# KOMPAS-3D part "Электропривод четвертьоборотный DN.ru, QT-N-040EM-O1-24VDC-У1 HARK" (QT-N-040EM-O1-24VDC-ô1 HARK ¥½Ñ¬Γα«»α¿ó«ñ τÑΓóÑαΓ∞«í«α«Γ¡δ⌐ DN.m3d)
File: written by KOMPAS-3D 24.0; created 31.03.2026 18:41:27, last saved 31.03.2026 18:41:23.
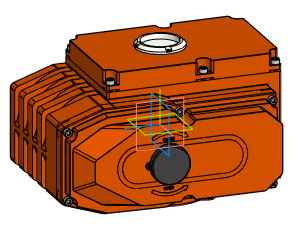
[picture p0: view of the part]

Document properties: Автор: DN.RU; Полное имя файла: D:\PROJECT CAD\DN.RU\...195\Исходники\24В\QT-N-040EM-O1-24VDC-У1 HARK Электропривод четвертьоборотный DN.ru\QT-N-040EM-O1-24VDC-У1 HARK Электропривод четвертьоборотный DN.m3d

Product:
- Body: Твердое тело1  | qty 1
    Масса: 37.407802
- Part/product: Электропривод четвертьоборотный DN.ru  | designation QT-N-040EM-O1-24VDC-У1 HARK
    Масса: 8.9
    Раздел спецификации: Прочие изделия
    Комментарий: D300-05873
    Примечание: D300-12506
    additional columns: Сталь

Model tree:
1. Твердое тело1  (labels: Твердое тело1)

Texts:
  QT-N-040EM-O1-24VDC-У1 HARK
